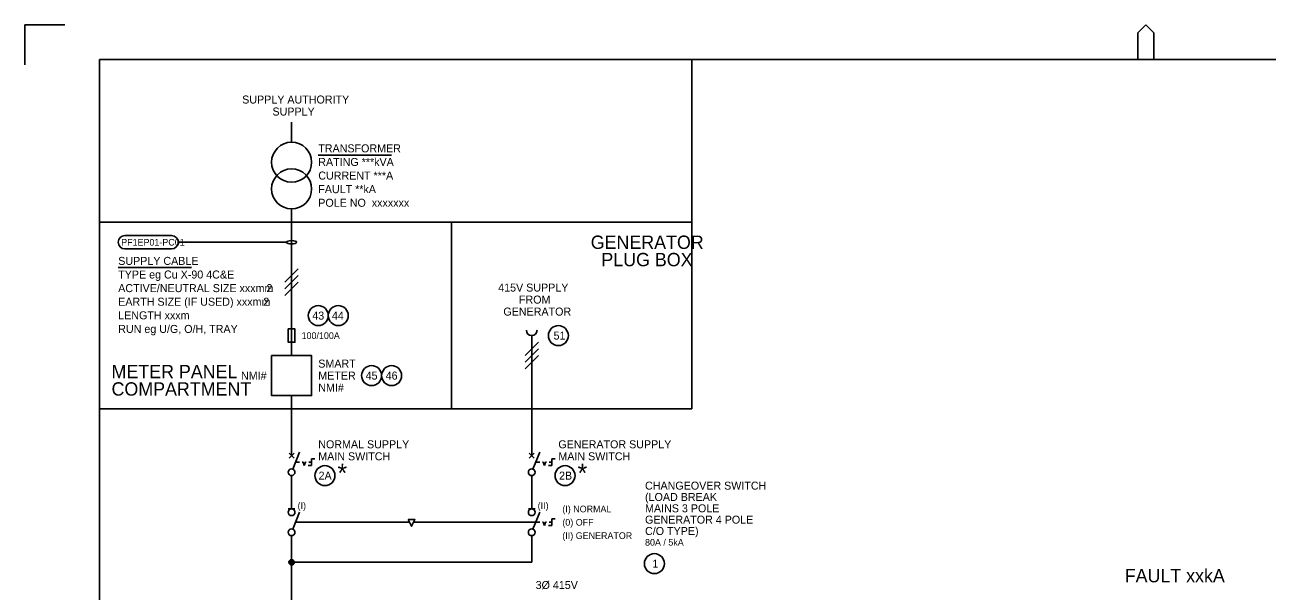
# Model space of a CAD drawing. Extents: x 0 to 841, y 0 to 594.
# Drawn here: x 0 to 465.7, y 381.7 to 594 of the extents above; entities that cross this region are included whole.
import ezdxf

# ---------------------------------------------------------------- set-up
doc = ezdxf.new("R2010")
doc.units = 0
for name, color, linetype in [('A1BORDER', 7, 'Continuous'), ('BASE', 7, 'Continuous'), ('Level 1', 7, 'Continuous'), ('Level 10', 7, 'Continuous')]:
    doc.layers.add(name, color=color, linetype=linetype)

msp = doc.modelspace()

# ---------------------------------------------------------------- linework, layer by layer
at = {"layer": 'A1BORDER'}
for p, q in [((0, 594), (15, 594)), ((0, 579), (0, 594)), ((417.19, 591), (420.19, 594)), ((423.19, 591), (420.19, 594)), ((417.19, 581), (417.19, 591)), ((423.19, 581), (423.19, 591)), ((28, 581), (829, 581)), ((28, 581), (28, 15))]:
    msp.add_line(p, q, dxfattribs=at)
at = {"layer": 'BASE'}
msp.add_line((98.125, 512.5), (57.5, 512.5), dxfattribs=at)
for points in [[(37.5, 515), (55, 515)], [(55, 510), (37.5, 510)]]:
    msp.add_lwpolyline(points, dxfattribs=at)
for centre, start, end in [((37.5, 512.5), 90, 270), ((55, 512.5), 270, 90)]:
    msp.add_arc(centre, 2.5, start, end, dxfattribs=at)
msp.add_ellipse((100, 512.5), major_axis=(-1.875, 0), ratio=0.333333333, dxfattribs=at)
at = {"layer": 'Level 1'}
for p, q in [((250, 450), (250, 581)), ((100, 550), (100, 557.5)), ((110, 545.2), (137.5, 545.2)), ((100, 470), (100, 525)), ((28, 520), (250, 520)), ((160, 450), (160, 520)), ((35, 503), (62.5, 503)), ((97.5, 497.5), (102.5, 502.5)), ((97.5, 495), (102.5, 500)), ((97.5, 492.5), (102.5, 497.5)), ((190, 435), (190, 477.5)), ((187.5, 470), (192.5, 475)), ((187.5, 467.5), (192.5, 472.5)), ((187.5, 465), (192.5, 470)), ((100, 435), (100, 455)), ((250, 450), (28, 450)), ((99.06, 433.44), (100.94, 431.56)), ((100.94, 433.44), (99.06, 431.56)), ((100, 432.5), (100, 435)), ((100.46, 427.41), (103, 433.75)), ((189.06, 433.44), (190.94, 431.56)), ((190.94, 433.44), (189.06, 431.56)), ((190, 432.5), (190, 435)), ((190.46, 427.41), (193, 433.75)), ((100, 412.5), (100, 425)), ((190, 412.5), (190, 425)), ((98.75, 412.5), (101.25, 412.5)), ((100.46, 404.91), (103, 411.25)), ((188.75, 412.5), (191.25, 412.5)), ((190.46, 404.91), (193, 411.25)), ((101.5, 407.5), (144.25, 407.5)), ((145.75, 407.5), (191.5, 407.5)), ((100, 352.5), (100, 402.5)), ((190, 392.5), (190, 402.5)), ((190, 392.5), (100, 392.5))]:
    msp.add_line(p, q, dxfattribs=at)
for points in [[(92.5, 470), (107.5, 470), (107.5, 455), (92.5, 455)], [(143.75, 408.5), (145, 406), (146.25, 408.5)]]:
    msp.add_lwpolyline(points, close=True, dxfattribs=at)
for centre, radius in [((100, 542.5), 7.5), ((100, 532.5), 7.5), ((110, 485), 3.75), ((117.5, 485), 3.75), ((200, 477.5), 3.75), ((130, 462.5), 3.75), ((137.5, 462.5), 3.75), ((112.5, 425), 3.75), ((202.5, 425), 3.75), ((100, 426.25), 1.25), ((190, 426.25), 1.25), ((100, 411.25), 1.25), ((190, 411.25), 1.25), ((100, 403.75), 1.25), ((190, 403.75), 1.25), ((236, 391.99997), 3.75)]:
    msp.add_circle(centre, radius, dxfattribs=at)
at = {"layer": 'Level 10'}
for p, q in [((101.5, 430), (103, 430)), ((104, 430), (104.33, 430)), ((104.75, 428.75), (104.33, 430)), ((104.75, 428.75), (105.17, 430)), ((105.5, 430), (105.17, 430)), ((106.25, 428.75), (107.5, 428.75)), ((106.5, 430), (107.5, 430)), ((107.5, 428.75), (107.5, 431.25)), ((107.5, 431.25), (108.75, 431.25)), ((191.5, 430), (193, 430)), ((194, 430), (194.33, 430)), ((194.75, 428.75), (194.33, 430)), ((194.75, 428.75), (195.17, 430)), ((195.5, 430), (195.17, 430)), ((196.25, 428.75), (197.5, 428.75)), ((196.5, 430), (197.5, 430)), ((197.5, 428.75), (197.5, 431.25)), ((197.5, 431.25), (198.75, 431.25)), ((191.5, 407.5), (193, 407.5)), ((194, 407.5), (194.33, 407.5)), ((194.75, 406.25), (194.33, 407.5)), ((194.75, 406.25), (195.17, 407.5)), ((195.5, 407.5), (195.17, 407.5)), ((196.25, 406.25), (197.5, 406.25)), ((196.5, 407.5), (197.5, 407.5)), ((197.5, 406.25), (197.5, 408.75)), ((197.5, 408.75), (198.75, 408.75)), ((99, 392.5), (100.99, 392.5)), ((99.05, 392.8), (100.95, 392.8)), ((99.05, 392.2), (100.95, 392.2)), ((99.2, 393.1), (100.8, 393.1)), ((99.2, 391.9), (100.8, 391.9)), ((99.56, 393.4), (100.44, 393.4)), ((99.56, 391.6), (100.44, 391.6)), ((100, 393.5), (100, 393.5))]:
    msp.add_line(p, q, dxfattribs=at)
msp.add_lwpolyline([(100, 475), (101.25, 475), (101.25, 480), (98.75, 480), (98.75, 475), (100, 475)], dxfattribs=at)
msp.add_circle((100, 392.5), 1, dxfattribs=at)
msp.add_arc((190, 479.5), 2, 180, 0, dxfattribs=at)

# ---------------------------------------------------------------- texts
at = {"layer": 'BASE'}
msp.add_text('PF1EP01-PC01', height=2.5, dxfattribs=at).set_placement((36.125, 511.25))
at = {"layer": 'Level 1'}
for s, height, p in [('SUPPLY AUTHORITY', 3, (81.47266, 564.5)), ('SUPPLY', 3, (92.82812, 560)), ('TRANSFORMER', 3, (110, 546.2)), ('RATING ***kVA', 3, (110, 541.1)), ('CURRENT ***A', 3, (110, 536)), ('FAULT **kA', 3, (110, 530.9)), ('POLE NO  xxxxxxx', 3, (110, 525.8)), ('GENERATOR', 5, (212.13867, 510)), ('PLUG BOX', 5, (216.12305, 503.5)), ('SUPPLY CABLE', 3, (35, 504)), ('TYPE eg Cu X-90 4C&E', 3, (35, 498.9)), ('ACTIVE/NEUTRAL SIZE xxxmm', 3, (35, 493.8)), ('2', 3, (90.58203, 493.8)), ('415V SUPPLY', 3, (177.44922, 494)), ('EARTH SIZE (IF USED) xxxmm', 3, (35, 488.7)), ('2', 3, (89.38672, 488.7)), ('FROM', 3, (185.21875, 489.5)), ('LENGTH xxxm', 3, (35, 483.6)), ('43', 3, (107.75879, 483.5)), ('44', 3, (115.10938, 483.5)), ('GENERATOR', 3, (179.3916, 485)), ('RUN eg U/G, O/H, TRAY', 3, (35, 478.5)), ('100/100A', 2.50002, (103.75, 476.24999)), ('51', 3, (198.20703, 476)), ('METER PANEL', 5, (32.5, 461.5)), ('SMART', 3, (110, 465.5)), ('NMI#', 3, (81.03516, 461)), ('METER', 3, (110, 461)), ('45', 3, (127.75879, 461)), ('46', 3, (135.25879, 461)), ('COMPARTMENT', 5, (32.5, 455)), ('NMI#', 3, (110, 456.5)), ('NORMAL SUPPLY', 3, (110, 435.25)), ('GENERATOR SUPPLY', 3, (200, 435.25)), ('MAIN SWITCH', 3, (110, 430.75)), ('MAIN SWITCH', 3, (200, 430.75)), ('*', 7, (117.21094, 422.5)), ('*', 7, (207.21094, 422.5)), ('2A', 3, (110.10938, 423.5)), ('2B', 3, (200.25879, 423.5)), ('CHANGEOVER SWITCH', 3, (232.5, 419.74999)), ('(I)', 2.5, (102.25, 412.5)), ('(II)', 2.5, (192.25, 412.5)), ('(LOAD BREAK', 3, (232.5, 415.49999)), ('(I) NORMAL', 2.50002, (201.5, 411.24999)), ('GENERATOR 4 POLE', 3, (232.5, 406.99999)), ('MAINS 3 POLE', 3, (232.5, 411.24999)), ('(0) OFF', 2.50002, (201.5, 406.24999)), ('C/O TYPE)', 3, (232.5, 402.74999)), ('(II) GENERATOR', 2.50002, (201.5, 401.24999)), ('80A / 5kA', 2.5, (232.5, 398.74999)), ('1', 3, (235.25293, 390.49997)), ('FAULT xxkA', 5, (412.32422, 385)), ('3Ø 415V', 3, (191.4834, 382.5))]:
    msp.add_text(s, height=height, dxfattribs=at).set_placement(p)

doc.saveas('drawing.dxf')
